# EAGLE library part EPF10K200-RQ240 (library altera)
EPF10K200 FLEX 10K family
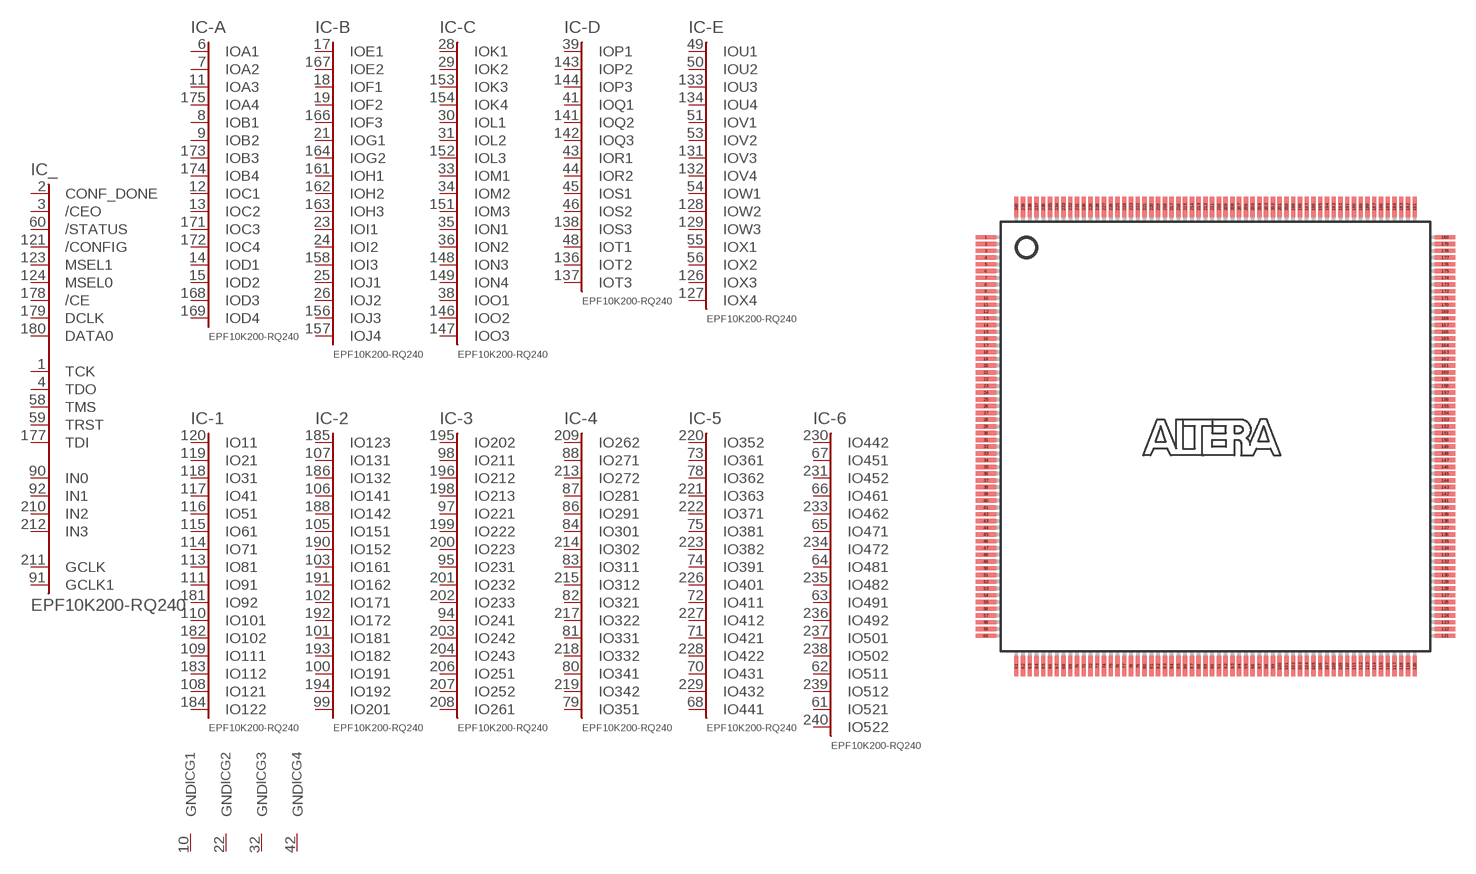
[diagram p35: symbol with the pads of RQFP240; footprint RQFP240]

Designator prefix IC; gates _=R240C -A=A4-D4 -B=E2-J4 -C=K4-O3 -D=P3-T3 -E=U4-X4 -1=122-200 -2=201-200 -3=261-200 -4=351-200 -5=441-200 -6=522-200 G1=GND G2=GND G3=GND G4=GND G5=GND G6=GND G7=GND G8=GND G9=GND G10=GND G11=GND G12=GND G13=GND G14=GND G15=GND G16=GND G17=GND G18=GND VI1=VCCINT VI2=VCCINT VI3=VCCINT VI4=VCCINT VI5=VCCINT VI6=VCCINT VI7=VCCINT VI8=VCCINT VI9=VCCINT VI10=VCCINT VI11=VCCINT VI12=VCCINT VI13=VCCINT VI14=VCCINT VI15=VCCINT VI16=VCCINT VO1=VCCIO VO2=VCCIO VO3=VCCIO VO4=VCCIO VO5=VCCIO VO6=VCCIO VO7=VCCIO VO8=VCCIO VO9=VCCIO VO10=VCCIO

## EPF10K200-RQ240 (MPN: EPF10K200SRC240-3N; OC_FARNELL: unknown; OC_NEWARK: 51R8934)  [RQFP240]
1  _:TCK
2  _:CONF_DONE  in
3  _:/CEO  in
4  _:TDO
5  VI1:VCC  pwr
6  -A:IOA1
7  -A:IOA2
8  -A:IOB1
9  -A:IOB2
10  G1:GND  pwr
11  -A:IOA3
12  -A:IOC1
13  -A:IOC2
14  -A:IOD1
15  -A:IOD2
16  VO1:VCCIO  pwr
17  -B:IOE1
18  -B:IOF1
19  -B:IOF2
20  VI2:VCC  pwr
21  -B:IOG1
22  G2:GND  pwr
23  -B:IOI1
24  -B:IOI2
25  -B:IOJ1
26  -B:IOJ2
27  VI3:VCC  pwr
28  -C:IOK1
29  -C:IOK2
30  -C:IOL1
31  -C:IOL2
32  G3:GND  pwr
33  -C:IOM1
34  -C:IOM2
35  -C:ION1
36  -C:ION2
37  VO2:VCCIO  pwr
38  -C:IOO1
39  -D:IOP1
40  VI4:VCC  pwr
41  -D:IOQ1
42  G4:GND  pwr
43  -D:IOR1
44  -D:IOR2
45  -D:IOS1
46  -D:IOS2
47  VI5:VCC  pwr
48  -D:IOT1
49  -E:IOU1
50  -E:IOU2
51  -E:IOV1
52  G5:GND  pwr
53  -E:IOV2
54  -E:IOW1
55  -E:IOX1
56  -E:IOX2
57  VO3:VCCIO  pwr
58  _:TMS
59  _:TRST
60  _:/STATUS  in
61  -6:IO521
62  -6:IO511
63  -6:IO491
64  -6:IO481
65  -6:IO471
66  -6:IO461
67  -6:IO451
68  -5:IO441
69  G6:GND  pwr
70  -5:IO431
71  -5:IO421
72  -5:IO411
73  -5:IO361
74  -5:IO391
75  -5:IO381
76  VI6:VCC  pwr
77  VO4:VCCIO  pwr
78  -5:IO362
79  -4:IO351
80  -4:IO341
81  -4:IO331
82  -4:IO321
83  -4:IO311
84  -4:IO301
85  G7:GND  pwr
86  -4:IO291
87  -4:IO281
88  -4:IO271
89  VI7:VCC  pwr
90  _:IN0  in
91  _:GCLK1  in
92  _:IN1  in
93  G8:GND  pwr
94  -3:IO241
95  -3:IO231
96  VI8:VCC  pwr
97  -3:IO221
98  -3:IO211
99  -2:IO201
100  -2:IO191
101  -2:IO181
102  -2:IO171
103  -2:IO161
104  G9:GND  pwr
105  -2:IO151
106  -2:IO141
107  -2:IO131
108  -1:IO121
109  -1:IO111
110  -1:IO101
111  -1:IO91
112  VO5:VCCIO  pwr
113  -1:IO81
114  -1:IO71
115  -1:IO61
116  -1:IO51
117  -1:IO41
118  -1:IO31
119  -1:IO21
120  -1:IO11
121  _:/CONFIG  in
122  VI9:VCC  pwr
123  _:MSEL1  in
124  _:MSEL0  in
125  G10:GND  pwr
126  -E:IOX3
127  -E:IOX4
128  -E:IOW2
129  -E:IOW3
130  VI10:VCC  pwr
131  -E:IOV3
132  -E:IOV4
133  -E:IOU3
134  -E:IOU4
135  G11:GND  pwr
136  -D:IOT2
137  -D:IOT3
138  -D:IOS3
139  VI11:VCC  pwr
140  VO6:VCCIO  pwr
141  -D:IOQ2
142  -D:IOQ3
143  -D:IOP2
144  -D:IOP3
145  G18:GND  pwr
146  -C:IOO2
147  -C:IOO3
148  -C:ION3
149  -C:ION4
150  VI12:VCC  pwr
151  -C:IOM3
152  -C:IOL3
153  -C:IOK3
154  -C:IOK4
155  G12:GND  pwr
156  -B:IOJ3
157  -B:IOJ4
158  -B:IOI3
159  VI13:VCC  pwr
160  VO7:VCCIO  pwr
161  -B:IOH1
162  -B:IOH2
163  -B:IOH3
164  -B:IOG2
165  G13:GND  pwr
166  -B:IOF3
167  -B:IOE2
168  -A:IOD3
169  -A:IOD4
170  VI14:VCC  pwr
171  -A:IOC3
172  -A:IOC4
173  -A:IOB3
174  -A:IOB4
175  -A:IOA4
176  G14:GND  pwr
177  _:TDI
178  _:/CE  in
179  _:DCLK  in
180  _:DATA0  in
181  -1:IO92
182  -1:IO102
183  -1:IO112
184  -1:IO122
185  -2:IO123
186  -2:IO132
187  VI15:VCC  pwr
188  -2:IO142
189  VO8:VCCIO  pwr
190  -2:IO152
191  -2:IO162
192  -2:IO172
193  -2:IO182
194  -2:IO192
195  -3:IO202
196  -3:IO212
197  G15:GND  pwr
198  -3:IO213
199  -3:IO222
200  -3:IO223
201  -3:IO232
202  -3:IO233
203  -3:IO242
204  -3:IO243
205  VO9:VCCIO  pwr
206  -3:IO251
207  -3:IO252
208  -3:IO261
209  -4:IO262
210  _:IN2  in
211  _:GCLK  in
212  _:IN3  in
213  -4:IO272
214  -4:IO302
215  -4:IO312
216  G16:GND  pwr
217  -4:IO322
218  -4:IO332
219  -4:IO342
220  -5:IO352
221  -5:IO363
222  -5:IO371
223  -5:IO382
224  VO10:VCCIO  pwr
225  VI16:VCC  pwr
226  -5:IO401
227  -5:IO412
228  -5:IO422
229  -5:IO432
230  -6:IO442
231  -6:IO452
232  G17:GND  pwr
233  -6:IO462
234  -6:IO472
235  -6:IO482
236  -6:IO492
237  -6:IO501
238  -6:IO502
239  -6:IO512
240  -6:IO522

## Footprint RQFP240 (pad centres in mm)
Power Quad Flat Pack
smd 1.5 x 0.32: 1 -17,14.75; 2 -17,14.25; 3 -17,13.75; 4 -17,13.25; 5 -17,12.75; 6 -17,12.25; 7 -17,11.75; 8 -17,11.25; 9 -17,10.75; 10 -17,10.25; 11 -17,9.75; 12 -17,9.25; 13 -17,8.75; 14 -17,8.25; 15 -17,7.75; 16 -17,7.25; 17 -17,6.75; 18 -17,6.25; 19 -17,5.75; 20 -17,5.25; 21 -17,4.75; 22 -17,4.25; 23 -17,3.75; 24 -17,3.25; 25 -17,2.75; 26 -17,2.25; 27 -17,1.75; 28 -17,1.25; 29 -17,0.75; 30 -17,0.25; 31 -17,-0.25; 32 -17,-0.75; 33 -17,-1.25; 34 -17,-1.75; 35 -17,-2.25; 36 -17,-2.75; 37 -17,-3.25; 38 -17,-3.75; 39 -17,-4.25; 40 -17,-4.75; 41 -17,-5.25; 42 -17,-5.75; 43 -17,-6.25; 44 -17,-6.75; 45 -17,-7.25; 46 -17,-7.75; 47 -17,-8.25; 48 -17,-8.75; 49 -17,-9.25; 50 -17,-9.75; 51 -17,-10.25; 52 -17,-10.75; 53 -17,-11.25; 54 -17,-11.75; 55 -17,-12.25; 56 -17,-12.75; 57 -17,-13.25; 58 -17,-13.75; 59 -17,-14.25; 60 -17,-14.75; 121 17,-14.75; 122 17,-14.25; 123 17,-13.75; 124 17,-13.25; 125 17,-12.75; 126 17,-12.25; 127 17,-11.75; 128 17,-11.25; 129 17,-10.75; 130 17,-10.25; 131 17,-9.75; 132 17,-9.25; 133 17,-8.75; 134 17,-8.25; 135 17,-7.75; 136 17,-7.25; 137 17,-6.75; 138 17,-6.25; 139 17,-5.75; 140 17,-5.25; 141 17,-4.75; 142 17,-4.25; 143 17,-3.75; 144 17,-3.25; 145 17,-2.75; 146 17,-2.25; 147 17,-1.75; 148 17,-1.25; 149 17,-0.75; 150 17,-0.25; 151 17,0.25; 152 17,0.75; 153 17,1.25; 154 17,1.75; 155 17,2.25; 156 17,2.75; 157 17,3.25; 158 17,3.75; 159 17,4.25; 160 17,4.75; 161 17,5.25; 162 17,5.75; 163 17,6.25; 164 17,6.75; 165 17,7.25; 166 17,7.75; 167 17,8.25; 168 17,8.75; 169 17,9.25; 170 17,9.75; 171 17,10.25; 172 17,10.75; 173 17,11.25; 174 17,11.75; 175 17,12.25; 176 17,12.75; 177 17,13.25; 178 17,13.75; 179 17,14.25; 180 17,14.75
smd 0.32 x 1.5: 61 -14.75,-17; 62 -14.25,-17; 63 -13.75,-17; 64 -13.25,-17; 65 -12.75,-17; 66 -12.25,-17; 67 -11.75,-17; 68 -11.25,-17; 69 -10.75,-17; 70 -10.25,-17; 71 -9.75,-17; 72 -9.25,-17; 73 -8.75,-17; 74 -8.25,-17; 75 -7.75,-17; 76 -7.25,-17; 77 -6.75,-17; 78 -6.25,-17; 79 -5.75,-17; 80 -5.25,-17; 81 -4.75,-17; 82 -4.25,-17; 83 -3.75,-17; 84 -3.25,-17; 85 -2.75,-17; 86 -2.25,-17; 87 -1.75,-17; 88 -1.25,-17; 89 -0.75,-17; 90 -0.25,-17; 91 0.25,-17; 92 0.75,-17; 93 1.25,-17; 94 1.75,-17; 95 2.25,-17; 96 2.75,-17; 97 3.25,-17; 98 3.75,-17; 99 4.25,-17; 100 4.75,-17; 101 5.25,-17; 102 5.75,-17; 103 6.25,-17; 104 6.75,-17; 105 7.25,-17; 106 7.75,-17; 107 8.25,-17; 108 8.75,-17; 109 9.25,-17; 110 9.75,-17; 111 10.25,-17; 112 10.75,-17; 113 11.25,-17; 114 11.75,-17; 115 12.25,-17; 116 12.75,-17; 117 13.25,-17; 118 13.75,-17; 119 14.25,-17; 120 14.75,-17; 181 14.75,17; 182 14.25,17; 183 13.75,17; 184 13.25,17; 185 12.75,17; 186 12.25,17; 187 11.75,17; 188 11.25,17; 189 10.75,17; 190 10.25,17; 191 9.75,17; 192 9.25,17; 193 8.75,17; 194 8.25,17; 195 7.75,17; 196 7.25,17; 197 6.75,17; 198 6.25,17; 199 5.75,17; 200 5.25,17; 201 4.75,17; 202 4.25,17; 203 3.75,17; 204 3.25,17; 205 2.75,17; 206 2.25,17; 207 1.75,17; 208 1.25,17; 209 0.75,17; 210 0.25,17; 211 -0.25,17; 212 -0.75,17; 213 -1.25,17; 214 -1.75,17; 215 -2.25,17; 216 -2.75,17; 217 -3.25,17; 218 -3.75,17; 219 -4.25,17; 220 -4.75,17; 221 -5.25,17; 222 -5.75,17; 223 -6.25,17; 224 -6.75,17; 225 -7.25,17; 226 -7.75,17; 227 -8.25,17; 228 -8.75,17; 229 -9.25,17; 230 -9.75,17; 231 -10.25,17; 232 -10.75,17; 233 -11.25,17; 234 -11.75,17; 235 -12.25,17; 236 -12.75,17; 237 -13.25,17; 238 -13.75,17; 239 -14.25,17; 240 -14.75,17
